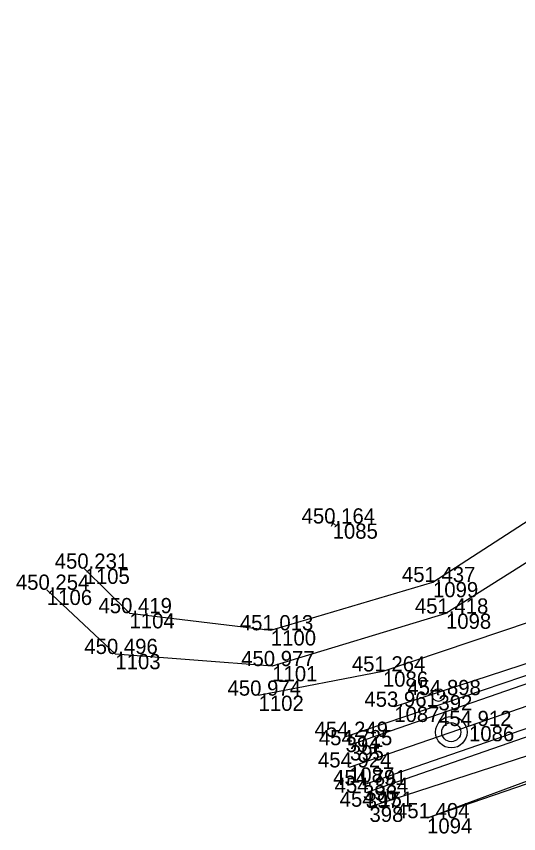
# Model space of a CAD drawing. Extents: x -751615 to -750797, y -1114905 to -1114561.
# Drawn here: x -751614.9 to -751575.2, y -1114846.6 to -1114782.1 of the extents above; entities that cross this region are included whole.
import ezdxf

# ---------------------------------------------------------------- set-up
doc = ezdxf.new("R2010")
doc.units = 0
for name, color, linetype in [('Vrstva 1', 7, 'Continuous'), ('Vrstva 4', 7, 'Continuous'), ('Vrstva 49', 7, 'Continuous'), ('Vrstva 51', 7, 'Continuous'), ('Vrstva 60', 7, 'Continuous'), ('Vrstva 61', 7, 'Continuous'), ('Vrstva 7', 7, 'Continuous')]:
    doc.layers.add(name, color=color, linetype=linetype)

msp = doc.modelspace()

# ---------------------------------------------------------------- linework, layer by layer
at = {"layer": 'Vrstva 1'}
msp.add_lwpolyline([(-751416.742, -1114782.09), (-751426.633, -1114785.503), (-751435.883, -1114788.699), (-751445.473, -1114792.007), (-751455.331, -1114795.406), (-751464.93, -1114798.717), (-751474.392, -1114801.982), (-751484.022, -1114805.308), (-751487.237, -1114806.416), (-751493.406, -1114808.538), (-751502.885, -1114811.809), (-751512.358, -1114815.079), (-751523.744, -1114819.014), (-751530.663, -1114821.401), (-751541.116, -1114825.002), (-751550.726, -1114828.317), (-751560.172, -1114831.578), (-751569.853, -1114834.918), (-751579.125, -1114838.113), (-751588.602, -1114841.381)], dxfattribs=at)
at = {"layer": 'Vrstva 4'}
for points in [[(-751531.222, -1114820.049), (-751532.411, -1114819.814), (-751547.631, -1114824.789), (-751568.7, -1114832.128), (-751588.868, -1114838.968)], [(-751531.222, -1114820.049), (-751547.578, -1114825.515), (-751568.497, -1114832.683), (-751588.528, -1114839.629)], [(-751529.854, -1114822.836), (-751546.799, -1114828.717), (-751567.35, -1114835.812), (-751587.5, -1114842.776)], [(-751529.854, -1114822.836), (-751530.62, -1114823.702), (-751546.636, -1114829.261), (-751567.254, -1114836.441), (-751587.282, -1114843.385)]]:
    msp.add_lwpolyline(points, dxfattribs=at)
at = {"layer": 'Vrstva 49'}
for p, q in [((-751589.669, -1114822.235), (-751590.119, -1114822.017)), ((-751589.785, -1114821.901), (-751590.003, -1114822.351)), ((-751534.993, -1114829.012), (-751582.438, -1114845.392))]:
    msp.add_line(p, q, dxfattribs=at)
for points in [[(-751564.092, -1114818.587), (-751543.018, -1114806.139), (-751536.934, -1114809.473), (-751533.922, -1114815.785), (-751539.386, -1114818.117), (-751585.925, -1114833.806), (-751595.742, -1114835.716)], [(-751535.601, -1114808.255), (-751531.347, -1114816.521), (-751539.042, -1114819.748), (-751551.843, -1114824.829), (-751553.747, -1114826.383), (-751585.03, -1114836.593)], [(-751586.983, -1114844.483), (-751566.691, -1114837.92), (-751546.322, -1114830.244), (-751529.778, -1114824.115), (-751528.71, -1114826.495)], [(-751535.416, -1114827.991), (-751582.438, -1114845.392)]]:
    msp.add_lwpolyline(points, dxfattribs=at)
at = {"layer": 'Vrstva 51'}
msp.add_lwpolyline([(-751609.483, -1114825.691), (-751605.933, -1114829.205), (-751594.773, -1114830.558), (-751581.97, -1114826.747), (-751566.399, -1114816.669), (-751540.967, -1114801.189), (-751532.595, -1114806.752), (-751528.368, -1114813.336), (-751525.848, -1114818.694), (-751529.358, -1114819.936), (-751530.249, -1114815.352), (-751535.601, -1114808.255), (-751541.69, -1114804.508), (-751564.092, -1114818.587), (-751580.945, -1114829.238), (-751594.664, -1114833.383), (-751607.051, -1114832.427), (-751612.458, -1114827.357)], dxfattribs=at)
at = {"layer": 'Vrstva 60'}
for p, q in [((-751589.894, -1114822.126), (-751589.894, -1114822.126)), ((-751609.483, -1114825.691), (-751609.483, -1114825.691)), ((-751581.97, -1114826.747), (-751581.97, -1114826.747)), ((-751612.458, -1114827.357), (-751612.458, -1114827.357)), ((-751605.933, -1114829.205), (-751605.933, -1114829.205)), ((-751580.945, -1114829.238), (-751580.945, -1114829.238)), ((-751594.773, -1114830.558), (-751594.773, -1114830.558)), ((-751607.051, -1114832.427), (-751607.051, -1114832.427)), ((-751594.664, -1114833.383), (-751594.664, -1114833.383)), ((-751585.925, -1114833.806), (-751585.925, -1114833.806)), ((-751595.742, -1114835.716), (-751595.742, -1114835.716)), ((-751581.537, -1114835.673), (-751581.537, -1114835.673)), ((-751585.03, -1114836.593), (-751585.03, -1114836.593)), ((-751579.125, -1114838.113), (-751579.125, -1114838.113)), ((-751588.868, -1114838.968), (-751588.868, -1114838.968)), ((-751588.528, -1114839.629), (-751588.528, -1114839.629)), ((-751588.602, -1114841.381), (-751588.602, -1114841.381)), ((-751587.5, -1114842.776), (-751587.5, -1114842.776)), ((-751587.282, -1114843.385), (-751587.282, -1114843.385)), ((-751586.983, -1114844.483), (-751586.983, -1114844.483)), ((-751582.438, -1114845.392), (-751582.438, -1114845.392))]:
    msp.add_line(p, q, dxfattribs=at)
at = {"layer": 'Vrstva 7'}
msp.add_line((-751581.49, -1114835.657), (-751581.584, -1114835.689), dxfattribs=at)
for centre, radius in [((-751581.537, -1114835.673), 0.5), ((-751580.529, -1114838.597), 1.246), ((-751580.529, -1114838.597), 0.752)]:
    msp.add_circle(centre, radius, dxfattribs=at)

# ---------------------------------------------------------------- texts
at = {"layer": 'Vrstva 60'}
for s, p in [('1085', (-751589.894, -1114823.326)), ('1105', (-751609.483, -1114826.891)), ('1099', (-751581.97, -1114827.947)), ('1106', (-751612.458, -1114828.557)), ('1104', (-751605.933, -1114830.405)), ('1098', (-751580.945, -1114830.438)), ('1100', (-751594.773, -1114831.758)), ('1103', (-751607.051, -1114833.627)), ('1101', (-751594.664, -1114834.583)), ('1086', (-751585.925, -1114835.006)), ('1102', (-751595.742, -1114836.916)), ('392', (-751581.537, -1114836.873)), ('1087', (-751585.03, -1114837.793)), ('1086', (-751579.125, -1114839.313)), ('394', (-751588.868, -1114840.168)), ('395', (-751588.528, -1114840.829)), ('1087', (-751588.602, -1114842.581)), ('396', (-751587.5, -1114843.976)), ('397', (-751587.282, -1114844.585)), ('398', (-751586.983, -1114845.683)), ('1094', (-751582.438, -1114846.592))]:
    msp.add_text(s, height=1.2, dxfattribs=at).set_placement(p)
at = {"layer": 'Vrstva 61'}
for s, p in [('450.164', (-751592.345, -1114822.126)), ('450.231', (-751611.84, -1114825.691)), ('451.437', (-751584.422, -1114826.747)), ('450.254', (-751614.909, -1114827.357)), ('450.419', (-751608.387, -1114829.205)), ('451.418', (-751583.399, -1114829.238)), ('451.013', (-751597.225, -1114830.558)), ('450.496', (-751609.503, -1114832.427)), ('450.977', (-751597.116, -1114833.383)), ('451.264', (-751588.376, -1114833.806)), ('450.974', (-751598.193, -1114835.716)), ('454.898', (-751583.991, -1114835.673)), ('453.961', (-751587.387, -1114836.593)), ('454.912', (-751581.573, -1114838.113)), ('454.249', (-751591.322, -1114838.968)), ('454.725', (-751590.984, -1114839.629)), ('454.924', (-751591.053, -1114841.381)), ('454.791', (-751589.857, -1114842.776)), ('454.334', (-751589.733, -1114843.385)), ('454.151', (-751589.34, -1114844.483)), ('451.404', (-751584.889, -1114845.392))]:
    msp.add_text(s, height=1.2, dxfattribs=at).set_placement(p)

doc.saveas('drawing.dxf')
